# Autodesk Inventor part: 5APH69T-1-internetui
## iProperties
Created: 2010-11
Part Number: 5APH69T-1-internetui
Document SubType Name: Modeling
Designer: Darius
Author: Darius
Translation Standard: STEP AP203
File Name: 5APH69T-1.STEP
Preprocessor: SolidWorks 2003240
Postprocessor: Build: 272, Release: 10 SP3a - Date: Thu 12/15/2005
Sent Units: MILLIMETERS
Uncertainty: 1e-05
